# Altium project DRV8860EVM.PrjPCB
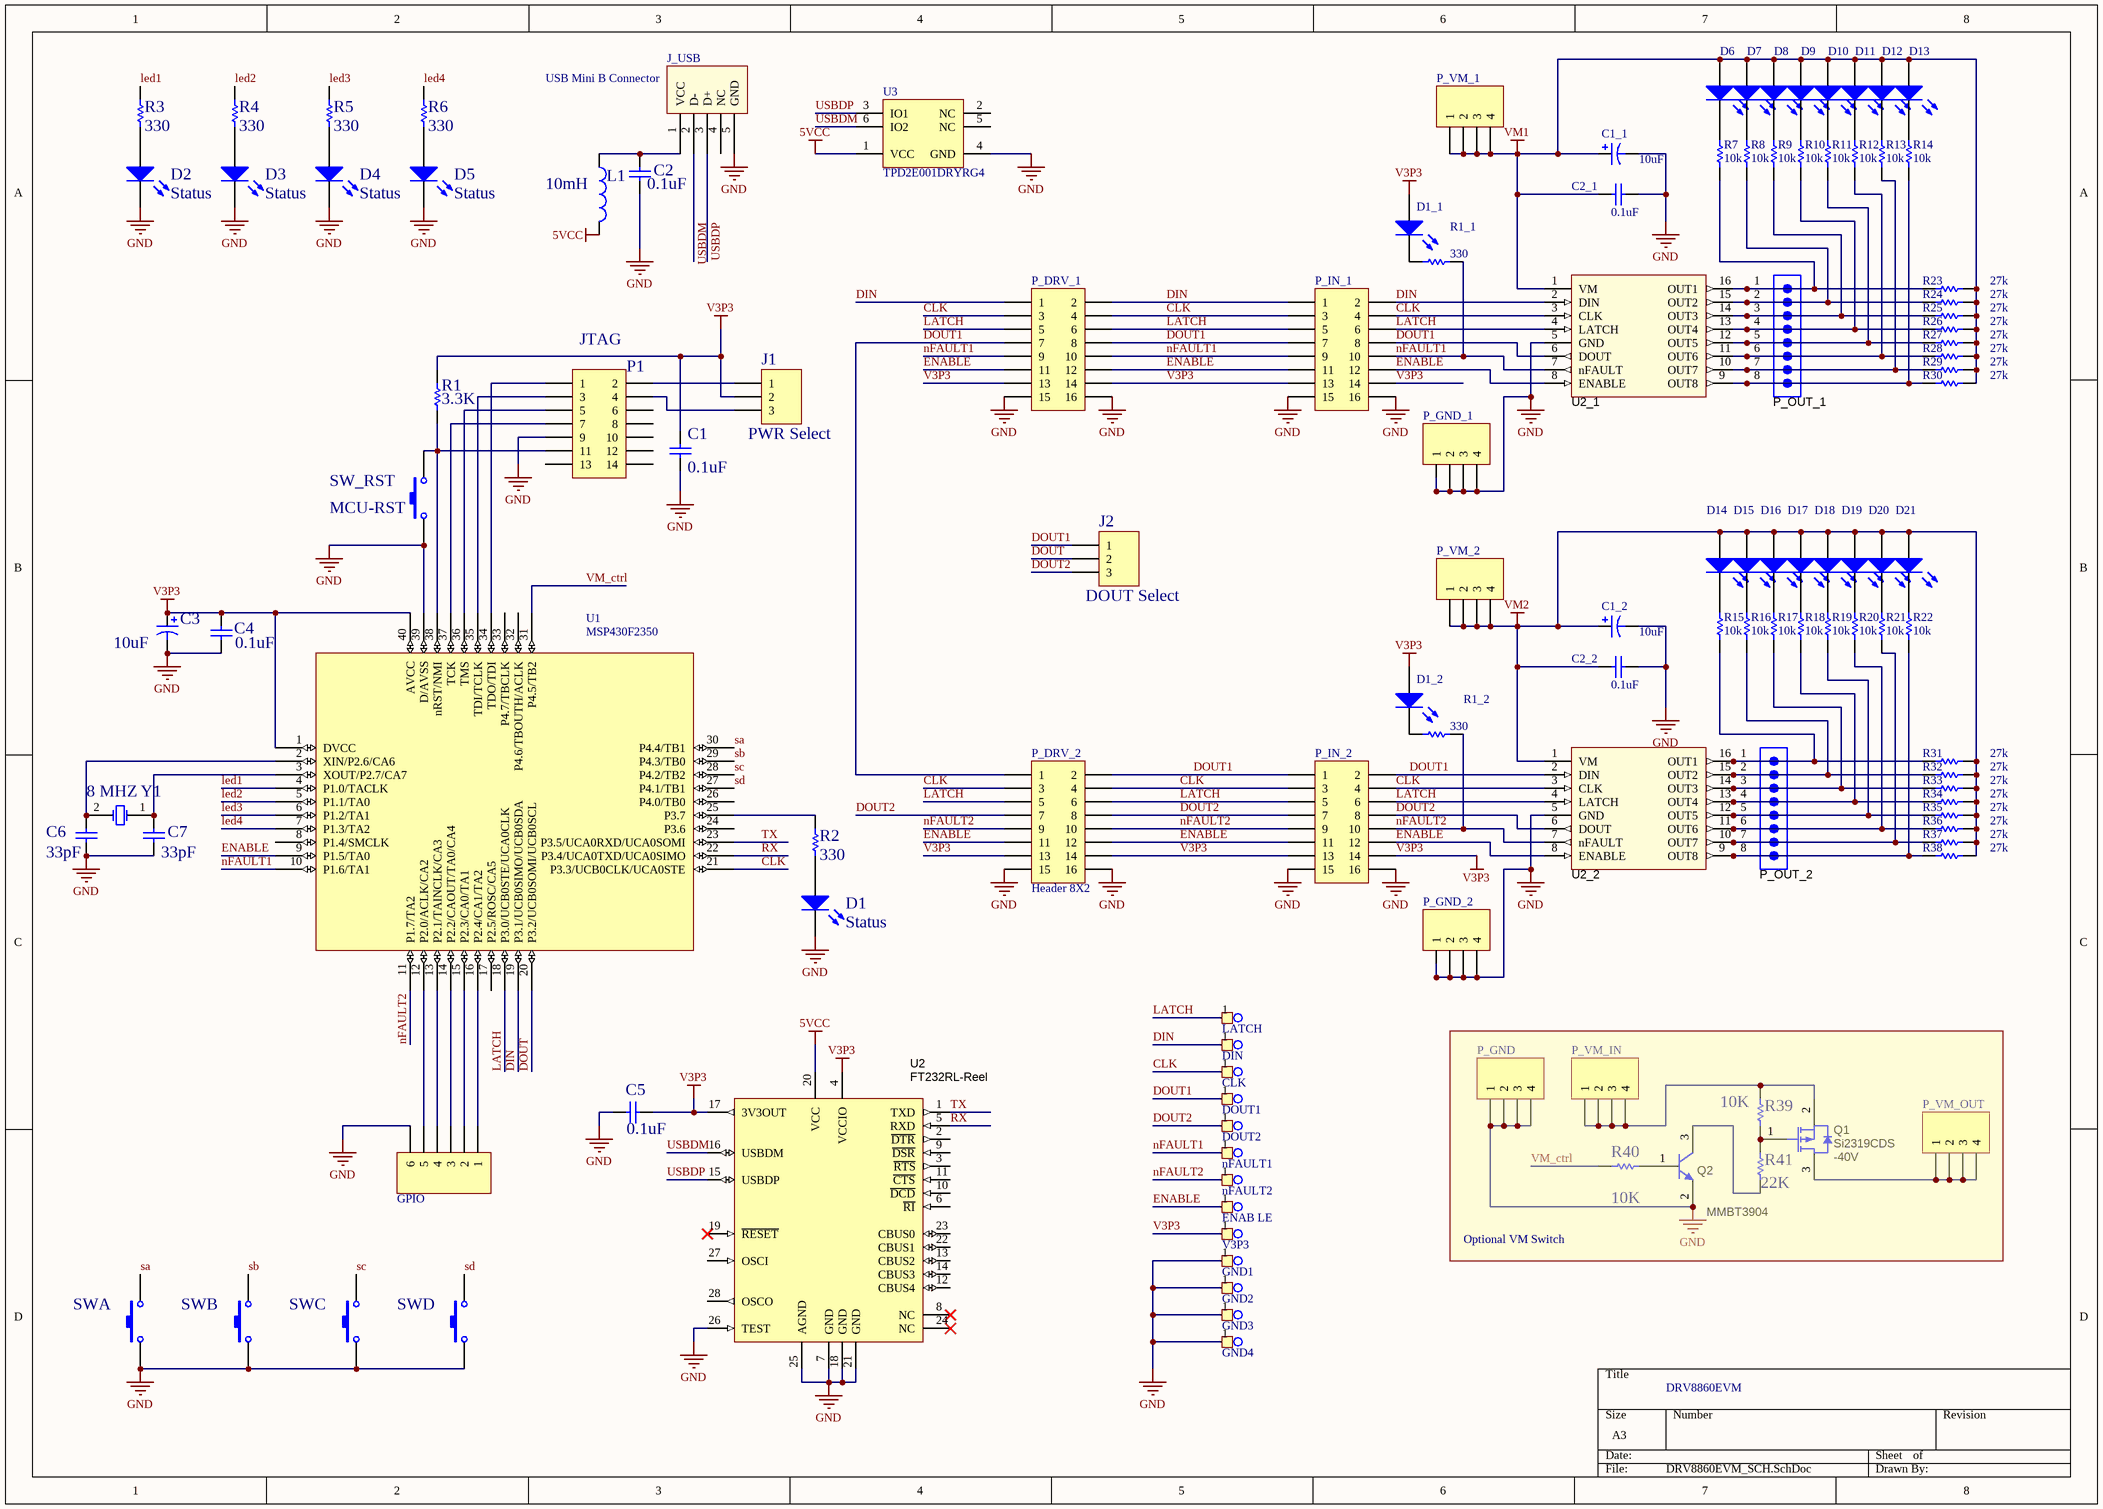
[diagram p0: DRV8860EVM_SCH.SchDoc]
1 sheet, 122 parts. Net scope: global (net labels, ports and power ports of the same name join across sheets).
Board file: DRV8860EVM_PCB.PcbDoc

## Sheet DRV8860EVM_SCH.SchDoc
size A3

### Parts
C1  value 0.1uF  [c0603]  (hidden comment: Cap)
C1_1  value 10uF  [1210]
C1_2  value 10uF  [1210]
C2  value 0.1uF  [c0603]  (hidden comment: Cap)
C2_1  value 0.1uF  [c0603]
C2_2  value 0.1uF  [c0603]
C3  value 10uF  [cap5mm]  (hidden comment: Cap Pol1)
C4  value 0.1uF  [c0603]  (hidden comment: Cap)
C5  value 0.1uF  [c0603]  (hidden comment: Cap)
C6  value 33pF  [c0603]  (hidden comment: Cap)
C7  value 33pF  [c0603]  (hidden comment: Cap)
CLK  IN1  [testp]  (value not drawn)
D1  Status  [3.2X1.6X1.1]
D1_1  nFAULT  [3.2X1.6X1.1]  (value not drawn)
D1_2  FAULTn  [3.2X1.6X1.1]  (value not drawn)
D2  Status  [3.2X1.6X1.1]
D3  Status  [3.2X1.6X1.1]
D4  Status  [3.2X1.6X1.1]
D5  Status  [3.2X1.6X1.1]
D6  (no value)  [3.2X1.6X1.1]
D7  (no value)  [3.2X1.6X1.1]
D8  (no value)  [3.2X1.6X1.1]
D9  (no value)  [3.2X1.6X1.1]
D10  (no value)  [3.2X1.6X1.1]
D11  (no value)  [3.2X1.6X1.1]
D12  (no value)  [3.2X1.6X1.1]
D13  (no value)  [3.2X1.6X1.1]
D14  (no value)  [3.2X1.6X1.1]
D15  (no value)  [3.2X1.6X1.1]
D16  (no value)  [3.2X1.6X1.1]
D17  (no value)  [3.2X1.6X1.1]
D18  (no value)  [3.2X1.6X1.1]
D19  (no value)  [3.2X1.6X1.1]
D20  (no value)  [3.2X1.6X1.1]
D21  (no value)  [3.2X1.6X1.1]
DIN  IN1  [testp]  (value not drawn)
DOUT1  IN1  [testp]  (value not drawn)
DOUT2  IN1  [testp]  (value not drawn)
ENAB_LE  IN1  [testp]  (value not drawn)
GND1  IN1  [testp]  (value not drawn)
GND2  IN1  [testp]  (value not drawn)
GND3  IN1  [testp]  (value not drawn)
GND4  IN1  [testp]  (value not drawn)
GPIO  Header 6  [HDR1X6]  (value not drawn)
J1  PWR Select  [HDR1X3]
J2  DOUT Select  [HDR1X3]
J_USB  USB Mini B Connector  [Micro USB AB]
L1  value 10mH  [r0603]
LATCH  IN1  [testp]  (value not drawn)
nFAULT1  IN1  [testp]  (value not drawn)
nFAULT2  IN1  [testp]  (value not drawn)
P1  JTAG  [hdr2x7]
P_DRV_1  Header 8X2  [HDR2X8]  (value not drawn)
P_DRV_2  Header 8X2  [HDR2X8]
P_GND  Header 4  [HDR1X4]  (value not drawn)
P_GND_1  Header 4  [HDR1X4]  (value not drawn)
P_GND_2  Header 4  [HDR1X4]  (value not drawn)
P_IN_1  Header 8X2  [HDR2X8]  (value not drawn)
P_IN_2  Header 8X2  [HDR2X8]  (value not drawn)
P_OUT_1  TSW-108-07-G-S  [hdr1x8]  (value not drawn)
P_OUT_2  TSW-108-07-G-S  [hdr1x8]  (value not drawn)
P_VM_1  Header 4  [HDR1X4]  (value not drawn)
P_VM_2  Header 4  [HDR1X4]  (value not drawn)
P_VM_IN  Header 4  [HDR1X4]  (value not drawn)
P_VM_OUT  Header 4  [HDR1X4]  (value not drawn)
Q1  Si2319CDS  value -40V  [SOT-23]
Q2  MMBT3904  [SOT-23]
R1  value 3.3K  [r0603]
R1_1  330  [r0603]
R1_2  330  [r0603]
R2  value 330  [r0603]  (hidden comment: Res2)
R3  value 330  [r0603]  (hidden comment: Res2)
R4  value 330  [r0603]  (hidden comment: Res2)
R5  value 330  [r0603]  (hidden comment: Res2)
R6  value 330  [r0603]  (hidden comment: Res2)
R7  10k  [r0603]
R8  10k  [r0603]
R9  10k  [r0603]
R10  10k  [r0603]
R11  10k  [r0603]
R12  10k  [r0603]
R13  10k  [r0603]
R14  10k  [r0603]
R15  10k  [r0603]
R16  10k  [r0603]
R17  10k  [r0603]
R18  10k  [r0603]
R19  10k  [r0603]
R20  10k  [r0603]
R21  10k  [r0603]
R22  10k  [r0603]
R23  27k  [r0603]
R24  27k  [r0603]
R25  27k  [r0603]
R26  27k  [r0603]
R27  27k  [r0603]
R28  27k  [r0603]
R29  27k  [r0603]
R30  27k  [r0603]
R31  27k  [r0603]
R32  27k  [r0603]
R33  27k  [r0603]
R34  27k  [r0603]
R35  27k  [r0603]
R36  27k  [r0603]
R37  27k  [r0603]
R38  27k  [r0603]
R39  value 10K  [r0603]
R40  value 10K  [r0603]
R41  value 22K  [r0603]
SW_RST  MCU-RST  [swww]
SWA  MCU-RST  [swww]  (value not drawn)
SWB  MCU-RST  [swww]  (value not drawn)
SWC  MCU-RST  [swww]  (value not drawn)
SWD  MCU-RST  [swww]  (value not drawn)
U1  MSP430F2350  [qfn40]
U2  FT232RL-Reel  [SSOP28]
U2_1  Wolfteeth  (value not drawn)
U2_2  Wolfteeth  (value not drawn)
U3  TPD2E001DRYRG4  [DRY0006A]
V3P3  IN1  [testp]  (value not drawn)
Y1  8 MHZ  [xtal6]

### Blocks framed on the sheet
Optional VM Switch: P_GND P_VM_IN P_VM_OUT Q1 Q2 R39-R41

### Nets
5VCC: L1.2 U2.20(VCC) U3.1(VCC)
GND: C1.1 C1_1.2 C1_2.2 C2.1 C2_1.2 C2_2.2 C3.2 C4.1 C5.2 C6.1 C7.1 D1.2(K) D2.2(K) D3.2(K) D4.2(K) D5.2(K) GND1.1 GND2.1 GND3.1 GND4.1 GPIO.6 J_USB.5(GND) P1.9 P_DRV_1.15 P_DRV_1.16 P_DRV_2.15 P_DRV_2.16 P_GND.1 P_GND.2 P_GND.3 P_GND.4 P_GND_1.1 P_GND_1.2 P_GND_1.3 P_GND_1.4 P_GND_2.1 P_GND_2.2 P_GND_2.3 P_GND_2.4 P_IN_1.15 P_IN_1.16 P_IN_2.15 P_IN_2.16 Q2.2(E) SW_RST.1 SWA.1 SWB.1 SWC.1 SWD.1 U1.39(D/AVSS) U2.7(GND) U2.18(GND) U2.21(GND) U2.25(AGND) U2.26(TEST) U2_1.5(GND) U2_2.5(GND) U3.4(GND)
V3P3: C1.2 C3.1 C4.2 C5.1 D1_1.1(A) D1_2.1(A) J1.2 P_DRV_1.13 P_DRV_1.14 P_DRV_2.13 P_DRV_2.14 P_IN_1.13 P_IN_1.14 P_IN_2.13 P_IN_2.14 R1.1 U1.1(DVCC) U1.40(AVCC) U2.4(VCCIO) U2.17(3V3OUT) V3P3.1
VM1: C1_1.1 C2_1.1 D6.1(A) D7.1(A) D8.1(A) D9.1(A) D10.1(A) D11.1(A) D12.1(A) D13.1(A) P_VM_1.1 P_VM_1.2 P_VM_1.3 P_VM_1.4 R23.2 R24.2 R25.2 R26.2 R27.2 R28.2 R29.2 R30.2 U2_1.1(VM)
VM2: C1_2.1 C2_2.1 D14.1(A) D15.1(A) D16.1(A) D17.1(A) D18.1(A) D19.1(A) D20.1(A) D21.1(A) P_VM_2.1 P_VM_2.2 P_VM_2.3 P_VM_2.4 R31.2 R32.2 R33.2 R34.2 R35.2 R36.2 R37.2 R38.2 U2_2.1(VM)
CLK: CLK.1 P_DRV_1.3 P_DRV_1.4 P_DRV_2.3 P_DRV_2.4 P_IN_1.3 P_IN_1.4 P_IN_2.3 P_IN_2.4 U1.21(P3.3/UCB0CLK/UCA0STE) U2_1.3(CLK) U2_2.3(CLK)
DIN: DIN.1 P_DRV_1.1 P_DRV_1.2 P_IN_1.1 P_IN_1.2 U1.19(P3.1/UCB0SIMO/UCB0SDA) U2_1.2(DIN)
DOUT: J2.2 U1.20(P3.2/UCB0SOMI/UCB0SCL)
DOUT1: DOUT1.1 J2.1 P_DRV_1.7 P_DRV_1.8 P_DRV_2.1 P_DRV_2.2 P_IN_1.7 P_IN_1.8 P_IN_2.1 P_IN_2.2 U2_1.6(DOUT) U2_2.2(DIN)
DOUT2: DOUT2.1 J2.3 P_DRV_2.7 P_DRV_2.8 P_IN_2.7 P_IN_2.8 U2_2.6(DOUT)
ENABLE: ENAB_LE.1 P_DRV_1.11 P_DRV_1.12 P_DRV_2.11 P_DRV_2.12 P_IN_1.11 P_IN_1.12 P_IN_2.11 P_IN_2.12 U1.9(P1.5/TA0) U2_1.8(ENABLE) U2_2.8(ENABLE)
LATCH: LATCH.1 P_DRV_1.5 P_DRV_1.6 P_DRV_2.5 P_DRV_2.6 P_IN_1.5 P_IN_1.6 P_IN_2.5 P_IN_2.6 U1.18(P3.0/UCB0STE/UCA0CLK) U2_1.4(LATCH) U2_2.4(LATCH)
led1: R3.2 U1.4(P1.0/TACLK)
led2: R4.2 U1.5(P1.1/TA0)
led3: R5.2 U1.6(P1.2/TA1)
led4: R6.2 U1.7(P1.3/TA2)
nFAULT1: nFAULT1.1 P_DRV_1.9 P_DRV_1.10 P_IN_1.9 P_IN_1.10 R1_1.1 U1.10(P1.6/TA1) U2_1.7(nFAULT)
nFAULT2: nFAULT2.1 P_DRV_2.9 P_DRV_2.10 P_IN_2.9 P_IN_2.10 R1_2.1 U1.11(P1.7/TA2) U2_2.7(nFAULT)
RX: U1.22(P3.4/UCA0TXD/UCA0SIMO) U2.5(RXD)
sa: SWA.2 U1.30(P4.4/TB1)
sb: SWB.2 U1.29(P4.3/TB0)
sc: SWC.2 U1.28(P4.2/TB2)
sd: SWD.2 U1.27(P4.1/TB1)
TX: U1.23(P3.5/UCA0RXD/UCA0SOMI) U2.1(TXD)
USBDM: J_USB.2(D-) U2.16(USBDM) U3.6(IO2)
USBDP: J_USB.3(D+) U2.15(USBDP) U3.3(IO1)
VM_ctrl: R40.1 U1.31(P4.5/TB2)
NetC2_2: C2.2 J_USB.1(VCC) L1.1
NetC6_2: C6.2 U1.2(XIN/P2.6/CA6) Y1.2(OSC2)
NetC7_2: C7.2 U1.3(XOUT/P2.7/CA7) Y1.1(OSC1)
NetD1_1: D1.1(A) R2.1
NetD1_1_2: D1_1.2(K) R1_1.2
NetD1_2_2: D1_2.2(K) R1_2.2
NetD2_1: D2.1(A) R3.1
NetD3_1: D3.1(A) R4.1
NetD4_1: D4.1(A) R5.1
NetD5_1: D5.1(A) R6.1
NetD6_2: D6.2(K) R7.1
NetD7_2: D7.2(K) R8.1
NetD8_2: D8.2(K) R9.1
NetD9_2: D9.2(K) R10.1
NetD10_2: D10.2(K) R11.1
NetD11_2: D11.2(K) R12.1
NetD12_2: D12.2(K) R13.1
NetD13_2: D13.2(K) R14.1
NetD14_2: D14.2(K) R15.1
NetD15_2: D15.2(K) R16.1
NetD16_2: D16.2(K) R17.1
NetD17_2: D17.2(K) R18.1
NetD18_2: D18.2(K) R19.1
NetD19_2: D19.2(K) R20.1
NetD20_2: D20.2(K) R21.1
NetD21_2: D21.2(K) R22.1
NetGPIO_1: GPIO.1 U1.16(P2.4/CA1/TA2)
NetGPIO_2: GPIO.2 U1.15(P2.3/CA0/TA1)
NetGPIO_3: GPIO.3 U1.14(P2.2/CAOUT/TA0/CA4)
NetGPIO_4: GPIO.4 U1.13(P2.1/TAINCLK/CA3)
NetGPIO_5: GPIO.5 U1.12(P2.0/ACLK/CA2)
NetJ1_1: J1.1 P1.2
NetJ1_3: J1.3 P1.4
NetP1_1: P1.1 U1.34(TDO/TDI)
NetP1_3: P1.3 U1.35(TDI/TCLK)
NetP1_5: P1.5 U1.36(TMS)
NetP1_7: P1.7 U1.37(TCK)
NetP1_11: P1.11 R1.2 SW_RST.2 U1.38(nRST/NMI)
NetP_OUT_1_1: P_OUT_1.1 R7.2 R23.1 U2_1.16(OUT1)
NetP_OUT_1_2: P_OUT_1.2 R8.2 R24.1 U2_1.15(OUT2)
NetP_OUT_1_3: P_OUT_1.3 R9.2 R25.1 U2_1.14(OUT3)
NetP_OUT_1_4: P_OUT_1.4 R10.2 R26.1 U2_1.13(OUT4)
NetP_OUT_1_5: P_OUT_1.5 R11.2 R27.1 U2_1.12(OUT5)
NetP_OUT_1_6: P_OUT_1.6 R12.2 R28.1 U2_1.11(OUT6)
NetP_OUT_1_7: P_OUT_1.7 R13.2 R29.1 U2_1.10(OUT7)
NetP_OUT_1_8: P_OUT_1.8 R14.2 R30.1 U2_1.9(OUT8)
NetP_OUT_2_1: P_OUT_2.1 R15.2 R31.1 U2_2.16(OUT1)
NetP_OUT_2_2: P_OUT_2.2 R16.2 R32.1 U2_2.15(OUT2)
NetP_OUT_2_3: P_OUT_2.3 R17.2 R33.1 U2_2.14(OUT3)
NetP_OUT_2_4: P_OUT_2.4 R18.2 R34.1 U2_2.13(OUT4)
NetP_OUT_2_5: P_OUT_2.5 R19.2 R35.1 U2_2.12(OUT5)
NetP_OUT_2_6: P_OUT_2.6 R20.2 R36.1 U2_2.11(OUT6)
NetP_OUT_2_7: P_OUT_2.7 R21.2 R37.1 U2_2.10(OUT7)
NetP_OUT_2_8: P_OUT_2.8 R22.2 R38.1 U2_2.9(OUT8)
NetP_VM_IN_1: P_VM_IN.1 P_VM_IN.2 P_VM_IN.3 P_VM_IN.4 Q1.2(S) R39.2
NetP_VM_OUT_1: P_VM_OUT.1 P_VM_OUT.2 P_VM_OUT.3 P_VM_OUT.4 Q1.3(D)
NetQ1_1: Q1.1(G) R39.1 R41.2
NetQ2_1: Q2.1(B) R40.2
NetQ2_3: Q2.3(C) R41.1
NetR2_2: R2.2 U1.25(P3.7)

Not connected (* = marked no-connect by the designer): J_USB 4(NC); P1 6 8 10 12 13 14; U1 8(P1.4/SMCLK) 17(P2.5/ROSC/CA5) 24(P3.6) 26(P4.0/TB0) 32(P4.6/TBOUTH/ACLK) 33(P4.7/TBCLK); U2 2(~{DTR}) 3(~{RTS}) 6(~{RI}) 8(NC)* 9(~{DSR}) 10(~{DCD}) 11(~{CTS}) 12(CBUS4) 13(CBUS2) 14(CBUS3) 19(~{RESET})* 22(CBUS1) 23(CBUS0) 24(NC)* 27(OSCI) 28(OSCO); U3 2(NC) 5(NC)

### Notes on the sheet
- DRV8860EVM

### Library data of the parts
C1 C2 C4 C5 = Cap: CAP .10UF 50V CERAMIC X7R 0805; MFG Part Number: CC0603ZRY5V9BB104; Manufacturer: Yageo; DK Part Number: 311-1343-1-ND
C1_1 C1_2 C3 = Cap Pol1: CAP ALUM 10UF 25V 20% RADIAL; MFG Part Number: UVR1E100MDD; Manufacturer: Nichicon; DK Part Number: 493-1057-ND
C2_1 C2_2 = Cap: Capacitor; Manufacturer: TDK; MFG Part Number: C1608X7S2A104M; DK Part Number: 445-5202-1-ND
C6 C7 = Cap: CAP CERAMIC 33PF 50V NP0 0805; MFG Part Number: C0603C0G1H330J; Manufacturer: TDK; DK Part Number: 445-1780-1-ND
CLK DIN DOUT1 DOUT2 ENAB_LE GND1-GND4 LATCH nFAULT1 nFAULT2 V3P3 = TEST POINT: PC TEST POINT MINIATURE SMT; Manufacturer: Keystone Electronics; MFG Part Number: 5019; Value: TP
D1-D5 = LED3: LED RED FACE UP 1206; MFG Part Number: LNJ211R82RA; Manufacturer: Panasonic; DK Part Number: P11532CT-ND; Value: Red LED
D1_1 D1_2 D6-D21 = LED2: LED RED FACE UP 1206; DK Part Number: P11532CT-ND; Manufacturer: Panasonic; MFG Part Number: LNJ211R82RA; Value: Red LED
GPIO = Header 6: Header, 6-Pin
J1 J2 = Header 3: CONN HEADER .100 SNGL STR 3POS; MFG Part Number: 929647-09-03-I; Manufacturer: 3M; DK Part Number: 929647-09-03-ND; Value: 3 Pos Header
J_USB = USB Mini B Recepticle: CONN RCPT MICRO USB TYPE AB; Manufacturer: TE Connectivity; MFG Part Number: 1981584-1; Value: Micro USB AB
L1 = Inductor: FERRITE 1.5A 40 OHM 0805 SMD; MFG Part Number: MI0805K400R-10; Manufacturer: Steward; DK Part Number: 240-2389-1-ND
P1 = Header 7X2H: CONN HEADER .100 DUAL STR 14POS; MFG Part Number: 929665-09-07-I; Manufacturer: 3M; DK Part Number: 929665-09-07-ND; Value: 14 Pos Header
P_DRV_1 P_DRV_2 P_IN_1 P_IN_2 = Header 8X2: Header, 8-Pin, Dual row
P_GND P_GND_1 P_GND_2 P_VM_1 P_VM_2 P_VM_IN P_VM_OUT = Header 4: Header, 4-Pin
P_OUT_1 P_OUT_2 = TSW-108-07-G-S: Header, TH, 100mil, 8x1, Gold plated, 230 mil above insulator; Manufacturer: Samtec, Inc.; Alternate Manufacturer: Any; Alternate PartNumber: Equivalent; U/M: EA
Q1 = SI2319DS-T1-E3: MOSFET, P-CH, -40V, -2.3A, SOT-23; Manufacturer: Vishay-Siliconix; Alternate Manufacturer: None; U/M: EA; ChType: P; VdsMax_V: -40; Value1: 0.13 ohm; Rdson45_Ohm: 0.13; Value2: 11.3 nC; QgTyp_nC: 11.3; Vgs_V: -20; IdsMax_A: -2.3
Q2 = MMBT3904, Fairchild Semiconductor: Transistor, NPN, 40V, 0.2A, SOT-23; CompType: BJT; PNP: 0; NPN: 1; Vceo_V: 40; Vcesat1_V: 0.2; Value: 0.2V; HfeMax: 300; TaMin_C: -55; TaMax_C: 150; U/M: EA
R1 R39-R41 = Res1: RES 3.3K OHM 1/10W 5% 0603 SMD; Manufacturer: Panasonic; MFG Part Number: ERJ-3GEYJ332V; DK Part Number: P3.3KGCT-ND
R1_1 R1_2 R7-R38 = Res1: Resistor; MFG Part Number: RC0603JR-07330RL; Manufacturer: Yageo; DK Part Number: 311-330GRCT-ND
R2-R6 = Res2: RES 330 OHM 1/8W 5% 0805 SMD; MFG Part Number: RC0603JR-07330RL; Manufacturer: Yageo; DK Part Number: 311-330GRCT-ND
SW_RST SWA SWB SWC SWD = SW-PB: SWITCH TACTILE SPST-NO 0.02A 15V; MFG Part Number: EVQ-11A04M; Manufacturer: Panasonic; DK Part Number: P8070SCT-ND; Value: Push Button
U1 = MSP430F2350: IC MCU 16BIT 16K FLASH 40-QFN; MFG Part Number: MSP430F2350IRHA; Manufacturer: Texas Instruments; DK Part Number: 296-22695-6-ND; Value: MSP430 MCU
U2 = FT232RL-Reel: USB UART Asynchronous Serial Data Transfer Chip, SSOP-28, Tape and Reel
U2_1 U2_2 = wolfteeth: Manufacturer: TI; SymbolVersion: use current date i.e. 2008-05-20; SymbolCreator: Use LDAP id; U/M: EA, IN, or GM; Description: 8 ch serial interface low-side driver IC
U3 = TPD2E001DRYRG4: Low-Capacitance + / - 15 kV ESD-Protection Array for High-Speed Data Interfaces, 2 Channels, -40 to +85 degC, 6-pin SON (DRY), Green (RoHS & no Sb/Br); Manufacturer: Texas Instruments; Alternate Manufacturer: None; Alternate PartNumber: Equivalent; Breakdown Voltage(Min)(V): 11; IEC 61000-4-2 Air-Gap(+/- kV): 15; IEC 61000-4-2 Contact(+/- kV): 8; IO Capacitance(Typ)(pF): 1.5; IO Leakage Current(nA): 1; SubFamily: ESD Solution; USB High Speed: TRUE
Y1 = XTAL: CRYSTAL 8.00 MHZ 20PF 49US; MFG Part Number: ECS-80-20-4; Manufacturer: ECS Inc.; DK Part Number: X165-ND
